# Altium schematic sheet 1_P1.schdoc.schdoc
size 220 x 160 mm; Symbol: Sheet-Symbol_A4; Device: Sheet-Symbol_A4; Company: 嘉立创EDA; Drawed: 一隅不独; Version: V1.0; Page Size: A4; @Project Name: RadiantStick; @Page Count: 1; @Update Date: 2024-03-23; @Create Date: 2024-03-13; @Schematic Name: Schematic1; @Page No: 1; @Page Name: P1
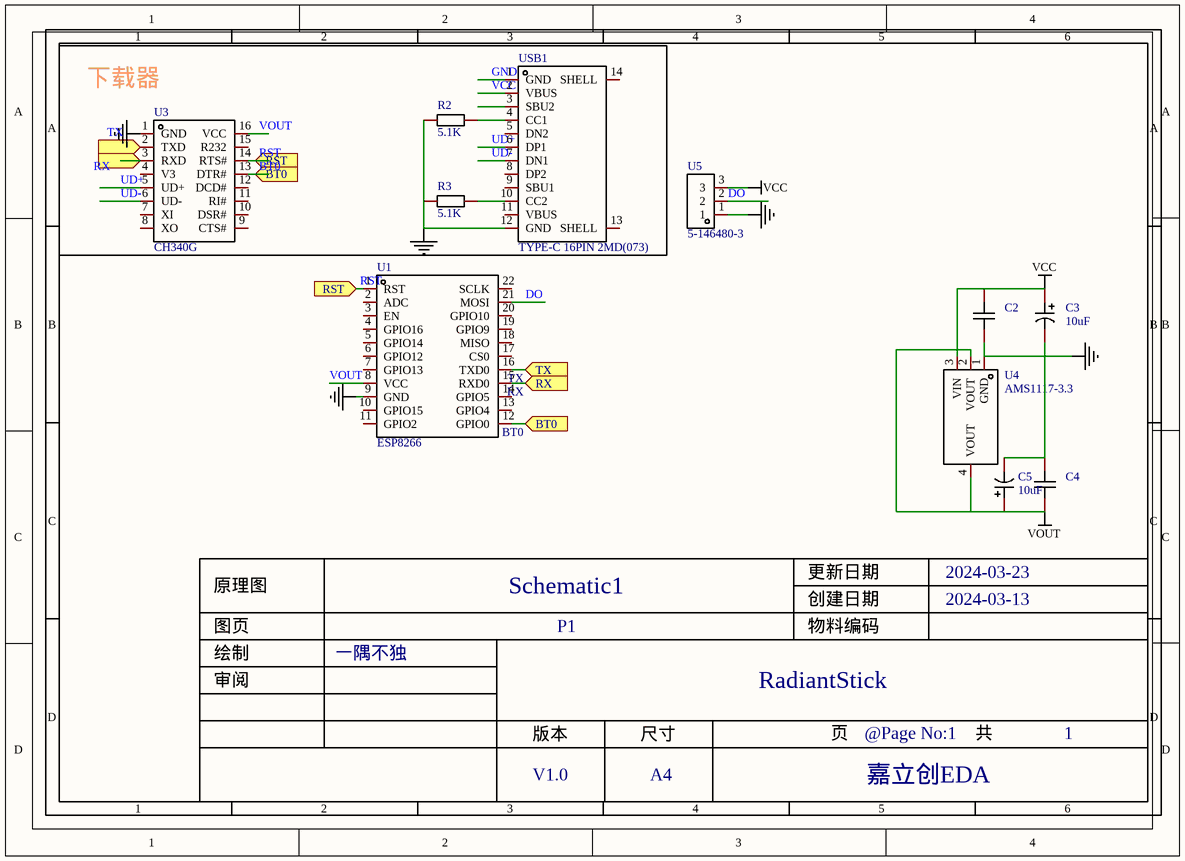
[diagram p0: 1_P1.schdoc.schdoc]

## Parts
C2  100nF  [C0603]  (value not drawn)
C3  10uF  [CAP-SMD_L3.5-W2.8-FD]
C4  CAP_0603  [C0603]  (value not drawn)
C5  10uF  [CAP-SMD_L3.5-W2.8-FD]
R2  5.1K  [R0603]
R3  5.1K  [R0603]
U1  ESP8266  [WIFIM-SMD_ESP-12F-ESP8266MOD]
U3  CH340G  [SOIC-16_L9.9-W3.9-P1.27-LS6.0-BL]
U4  AMS1117-3.3  [SOT-223-3_L6.5-W3.4-P2.30-LS7.0-BR]
U5  5-146480-3  [HDR-TH_3P-P2.54-V-M-2]
USB1  TYPE-C 16PIN 2MD(073)  [USB-C-SMD_TYPE-C-6PIN-2MD-073]

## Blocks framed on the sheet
下载器: R2 R3 U3 USB1

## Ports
 (in), BT0 (in), RST (in), RX (in), TX (in)

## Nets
NetC2_1: C2.1 C3.2 C4.1 C5.2 R2.1 R3.1 U1.9(GND) U3.1(GND) U4.1(GND) U5.1 USB1.12(GND)
VCC: C2.2 C3.1 U4.3(VIN) U5.3 USB1.2(VBUS)
VOUT: C4.2 C5.1 U1.8(VCC) U3.16(VCC) U4.2(VOUT) U4.4(VOUT)
BT0: U1.12(GPIO0) U3.13(DTR#) ; port BT0
DO: U1.21(MOSI) U5.2
GND: USB1.1(GND)
RST: U1.1(RST) U3.14(RTS#) ; port RST
RX: U1.15(RXD0) ; port RX
TX: U1.16(TXD0) ; port TX
UD+: U3.5(UD+) USB1.6(DP1)
UD-: U3.6(UD-) USB1.7(DN1)
NetR2_2: R2.2 USB1.4(CC1)
NetR3_2: R3.2 USB1.10(CC2)
NetU3_2: U3.2(TXD) U3.3(RXD) ; port 

Not connected (* = marked no-connect by the designer): U1 2(ADC) 3(EN) 4(GPIO16) 5(GPIO14) 6(GPIO12) 7(GPIO13) 10(GPIO15) 11(GPIO2) 13(GPIO4) 14(GPIO5) 17(CS0) 18(MISO) 19(GPIO9) 20(GPIO10) 22(SCLK); U3 4(V3) 7(XI) 8(XO) 9(CTS#) 10(DSR#) 11(RI#) 12(DCD#) 15(R232); USB1 3(SBU2) 5(DN2) 8(DP2) 9(SBU1) 11(VBUS) 13(SHELL) 14(SHELL)

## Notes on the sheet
- Labels drawn without touching a wire or pin: RX, TX

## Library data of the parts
C2 = CAP_0603: Symbol: CapAcitance; Convert to PCB: yes
C3 C5 = CA45A-B-20V-10UF-K: Manufacturer: CEC(振华新云); Add into BOM: yes; Tolerance: ±10%; Rated Voltage: 20V; Description: 容值:10uF;精度:±10%;额定电压:20V;
C4 = CAP_0603: Symbol: CapAcitance; Convert to PCB: yes; Value: 100nF
R2 R3 = Res_0603: Symbol: 电阻; Convert to PCB: yes
U1 = ESP8266: Add into BOM: yes
U3 = CH340G: Manufacturer: WCH(南京沁恒); Add into BOM: yes; Applications Function: 收发器; Protocol: USB 2.0; Supply Voltage: 3.3V；5V; Data Rate: 2Mbps; Description: 应用功能:收发器;接口协议:USB 2.0;数据速率:2Mbps;
U4 = AMS1117-3.3_C6186: Manufacturer: AMS; Add into BOM: yes; Output Type: 固定; Output Voltage: 3.3V; MAX Output Current: 1A; Power Supply Rejection Ratio (PSRR): 72dB@(120Hz); Dropout Voltage: 1.3V@(800mA); Output Polarity: 正极; Number of Outputs: 1; Description: 输出类型:固定;最大输入电压:-;输出电压:3.3V;最大输出电流:1A;电源纹波抑制比(PSRR):72dB@(120Hz);输出极性:正极;
U5 = 5-146480-3: Manufacturer: TE Connectivity(泰科电子); Add into BOM: yes
USB1 = TYPE-C 16PIN 2MD(073): Manufacturer: SHOU HAN(首韩); Add into BOM: yes; Gender: 母; Number of Ports: 1; Number of Contacts: 16P; Current Rating - Power (Max): 5A; Description: 连接器类型:Type-C;标准:-;公母:母;端口数量:1;触点数量:16P;安装方式:卧贴;额定电流 - 电源:5A;工作温度范围:-25℃~+85℃;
